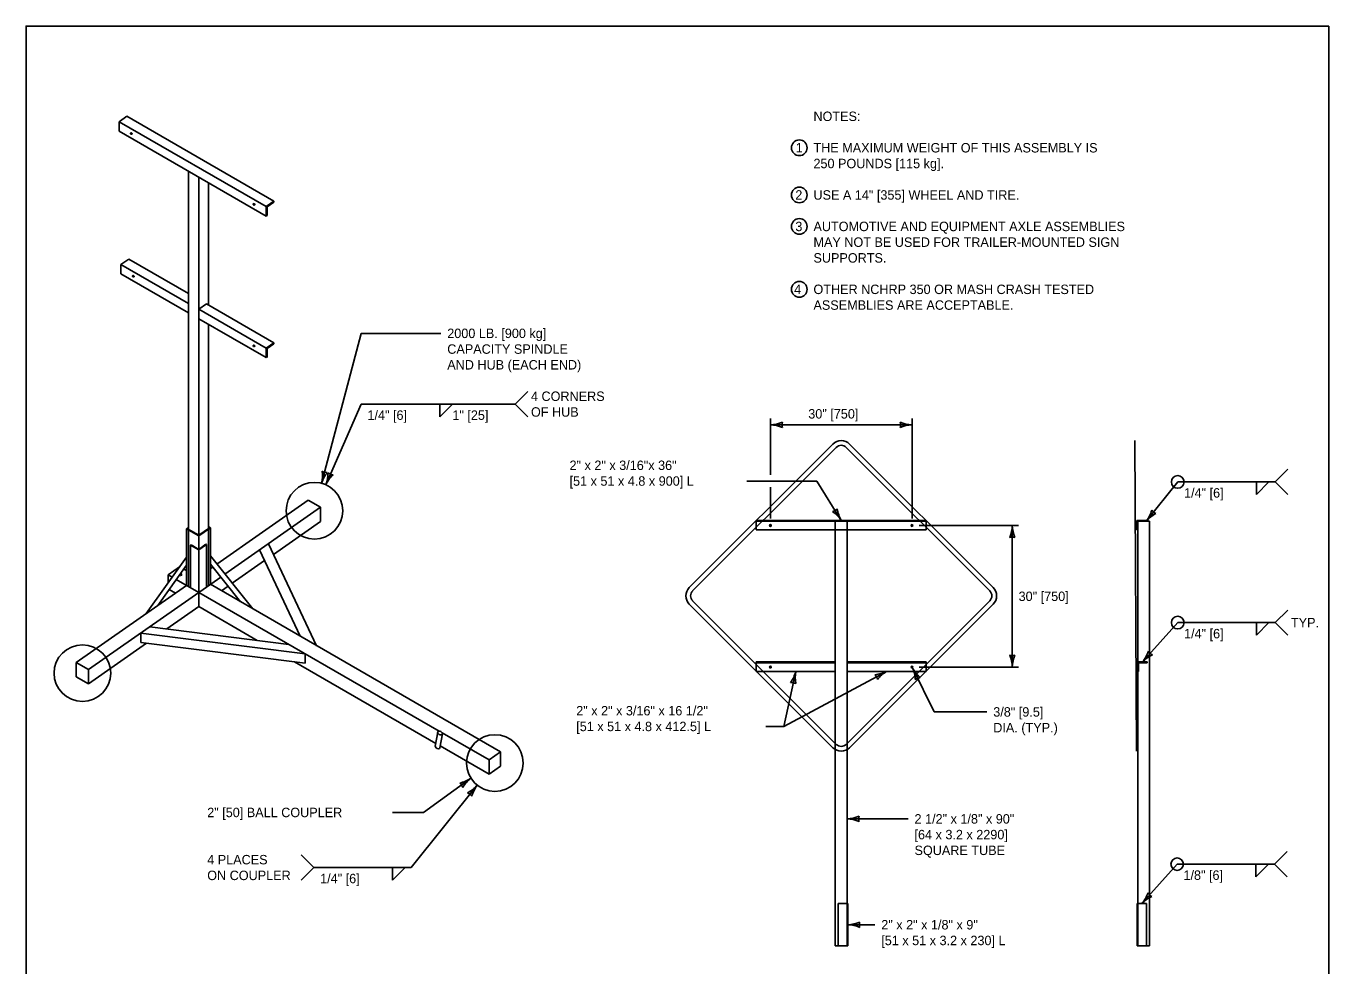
# Model space of a CAD drawing. Extents: x 49991.4 to 50021, y 49987.6 to 50011.4.
# Drawn here: x 50000.34 to 50008.61, y 50005.29 to 50011.26 of the extents above; entities that cross this region are included whole.
import ezdxf

# ---------------------------------------------------------------- set-up
doc = ezdxf.new("R2010")
doc.units = 0
for name, color, linetype in [('Level 1', 7, 'Continuous'), ('Level 2', 7, 'Continuous'), ('Level 3', 7, 'Continuous'), ('Level 4', 7, 'Continuous')]:
    doc.layers.add(name, color=color, linetype=linetype)

msp = doc.modelspace()

# ---------------------------------------------------------------- linework, layer by layer
at = {"layer": 'Level 1'}
for p, q in [((50000.9262, 50010.6548), (50000.9754, 50010.6891)), ((50000.9262, 50010.6548), (50001.8616, 50010.1148)), ((50000.9262, 50010.6548), (50000.9262, 50010.5948)), ((50000.9754, 50010.6891), (50001.9107, 50010.1491)), ((50000.9262, 50010.5948), (50001.8616, 50010.0548)), ((50001.3676, 50008.0639), (50001.3676, 50010.34)), ((50001.4329, 50008.0264), (50001.4329, 50010.3022)), ((50001.4941, 50009.4897), (50001.4941, 50010.267)), ((50001.8616, 50010.1148), (50001.9107, 50010.1491)), ((50001.8671, 50010.1131), (50001.9107, 50010.1436)), ((50001.9107, 50010.1491), (50001.9107, 50010.1436)), ((50001.8616, 50010.1148), (50001.8616, 50010.0548)), ((50001.8616, 50010.0548), (50001.8671, 50010.0586)), ((50001.8671, 50010.1131), (50001.8671, 50010.0586)), ((50000.9388, 50009.7475), (50000.988, 50009.7818)), ((50000.9388, 50009.7475), (50000.9388, 50009.6875)), ((50000.9388, 50009.7475), (50001.3676, 50009.4999)), ((50000.988, 50009.7818), (50001.3676, 50009.5627)), ((50000.9388, 50009.6875), (50001.3676, 50009.4399)), ((50001.4329, 50009.4622), (50001.4821, 50009.4967)), ((50001.4821, 50009.4967), (50001.9107, 50009.2491)), ((50001.4329, 50009.4622), (50001.8616, 50009.2148)), ((50001.4329, 50009.4022), (50001.8616, 50009.1548)), ((50001.4941, 50008.0692), (50001.4941, 50009.367)), ((50001.8616, 50009.2148), (50001.9107, 50009.2491)), ((50001.8671, 50009.2131), (50001.9107, 50009.2436)), ((50001.9107, 50009.2491), (50001.9107, 50009.2436)), ((50001.8616, 50009.2148), (50001.8616, 50009.1548)), ((50001.8616, 50009.1548), (50001.8671, 50009.1586)), ((50001.8671, 50009.2131), (50001.8671, 50009.1586)), ((50005.4624, 50008.6057), (50004.5501, 50007.6937)), ((50005.4839, 50008.5846), (50004.5714, 50007.6725)), ((50006.4595, 50007.6725), (50005.5475, 50008.5846)), ((50006.4807, 50007.6937), (50005.5682, 50008.6057)), ((50007.3805, 50008.6276), (50007.3927, 50006.6534)), ((50001.5481, 50007.8425), (50002.1291, 50008.2493)), ((50002.1291, 50008.2493), (50002.207, 50008.2043)), ((50001.5993, 50007.7788), (50002.207, 50008.2043)), ((50002.207, 50008.2043), (50002.207, 50008.1143)), ((50001.355, 50008.0672), (50001.3676, 50008.076)), ((50001.355, 50008.0672), (50001.4329, 50008.0222)), ((50001.355, 50007.7072), (50001.355, 50008.0672)), ((50001.3613, 50008.0675), (50001.3676, 50008.0719)), ((50001.3613, 50008.0675), (50001.4327, 50008.0263)), ((50001.4327, 50008.0263), (50001.5003, 50008.0736)), ((50001.4329, 50008.0222), (50001.5067, 50008.0738)), ((50001.4941, 50008.0812), (50001.5067, 50008.0738)), ((50001.4941, 50008.0772), (50001.5003, 50008.0736)), ((50001.5067, 50007.714), (50001.5067, 50008.0738)), ((50001.9073, 50007.9043), (50002.207, 50008.1143)), ((50004.9754, 50008.1206), (50006.0554, 50008.1206)), ((50004.9754, 50008.1206), (50004.9754, 50008.0606)), ((50004.9754, 50008.0606), (50006.0554, 50008.0606)), ((50005.4779, 50008.0606), (50005.4779, 50005.4151)), ((50005.5529, 50005.6851), (50005.5529, 50008.0606)), ((50006.0554, 50008.1206), (50006.0554, 50008.0606)), ((50007.394, 50008.1206), (50007.454, 50008.1206)), ((50007.394, 50008.0606), (50007.394, 50008.1206)), ((50007.3996, 50008.0606), (50007.394, 50008.0606)), ((50007.4746, 50008.1151), (50007.3996, 50008.1151)), ((50007.3996, 50008.1151), (50007.3996, 50005.6851)), ((50007.454, 50008.1151), (50007.454, 50008.1206)), ((50007.4746, 50008.1151), (50007.4746, 50005.4151)), ((50001.4329, 50007.6622), (50001.4329, 50008.0222)), ((50001.5067, 50007.894), (50001.7769, 50007.5579)), ((50001.8185, 50007.9322), (50002.0783, 50007.3839)), ((50001.8752, 50007.972), (50002.1822, 50007.3239)), ((50001.355, 50007.8872), (50001.0994, 50007.5283)), ((50001.355, 50007.8352), (50001.1732, 50007.58)), ((50001.238, 50007.7748), (50001.3113, 50007.8258)), ((50001.3379, 50007.8113), (50001.355, 50007.8014)), ((50001.5067, 50007.8419), (50001.6988, 50007.603)), ((50001.5067, 50007.8134), (50001.5213, 50007.8237)), ((50001.6456, 50007.7212), (50001.8505, 50007.8647)), ((50000.7325, 50007.1718), (50001.5726, 50007.76)), ((50001.238, 50007.7748), (50001.238, 50007.7229)), ((50001.238, 50007.7748), (50001.2641, 50007.7596)), ((50001.2904, 50007.7445), (50001.4329, 50007.6622)), ((50000.6545, 50007.2168), (50001.355, 50007.7072)), ((50001.245, 50007.6808), (50001.2845, 50007.6579)), ((50001.4329, 50007.6622), (50001.4329, 50007.5722)), ((50001.4329, 50007.6622), (50002.9596, 50006.7808)), ((50001.5067, 50007.714), (50003.3513, 50006.6488)), ((50001.5771, 50007.6732), (50001.6189, 50007.7024)), ((50006.4595, 50007.6724), (50006.4595, 50007.6725)), ((50006.4807, 50007.6936), (50006.4807, 50007.6937)), ((50001.2299, 50007.4301), (50001.4329, 50007.5722)), ((50001.4329, 50007.5722), (50001.8049, 50007.3574)), ((50004.5501, 50007.5874), (50005.4624, 50006.6754)), ((50004.5714, 50007.6089), (50005.4839, 50006.6964)), ((50005.5475, 50006.6964), (50006.4595, 50007.6089)), ((50005.5682, 50006.6754), (50006.4807, 50007.5874)), ((50001.0643, 50007.4041), (50002.1084, 50007.2722)), ((50001.0643, 50007.4041), (50001.0643, 50007.3441)), ((50001.1211, 50007.4438), (50002.0044, 50007.3322)), ((50000.7325, 50007.0818), (50001.1005, 50007.3395)), ((50001.0643, 50007.3441), (50002.1084, 50007.2122)), ((50002.1084, 50007.2722), (50002.1084, 50007.2122)), ((50000.6545, 50007.2168), (50000.6545, 50007.1268)), ((50000.6545, 50007.2168), (50000.7325, 50007.1718)), ((50000.7325, 50007.1718), (50000.7325, 50007.0818)), ((50002.0419, 50007.2206), (50002.9385, 50006.7029)), ((50005.4779, 50007.2206), (50004.9754, 50007.2206)), ((50004.9754, 50007.2206), (50004.9754, 50007.1606)), ((50005.4779, 50007.1606), (50004.9754, 50007.1606)), ((50006.0554, 50007.2206), (50005.5529, 50007.2206)), ((50006.0554, 50007.1606), (50005.5529, 50007.1606)), ((50006.0554, 50007.2206), (50006.0554, 50007.1606)), ((50007.3996, 50007.2206), (50007.4596, 50007.2206)), ((50007.4053, 50007.1606), (50007.3996, 50007.1606)), ((50007.4053, 50007.1606), (50007.4053, 50007.2151)), ((50007.4053, 50007.2151), (50007.4596, 50007.2151)), ((50007.4596, 50007.2151), (50007.4596, 50007.2206)), ((50000.6545, 50007.1268), (50000.7325, 50007.0818)), ((50002.9356, 50006.6861), (50002.9512, 50006.7748)), ((50002.9652, 50006.6746), (50002.9808, 50006.7632)), ((50002.9797, 50006.7692), (50003.2775, 50006.5972)), ((50002.9673, 50006.6864), (50003.2775, 50006.5072)), ((50003.3513, 50006.6488), (50003.2775, 50006.5972)), ((50003.2775, 50006.5972), (50003.2775, 50006.5072)), ((50003.3513, 50006.6488), (50003.3513, 50006.5588)), ((50003.3513, 50006.5588), (50003.2775, 50006.5072)), ((50005.5566, 50005.6851), (50005.4966, 50005.6851)), ((50005.4966, 50005.4151), (50005.4966, 50005.6851)), ((50005.5566, 50005.4151), (50005.5566, 50005.6851)), ((50007.3959, 50005.4151), (50007.3959, 50005.6851)), ((50007.3959, 50005.6851), (50007.4559, 50005.6851)), ((50007.4559, 50005.4151), (50007.4559, 50005.6851)), ((50005.4779, 50005.4151), (50005.5566, 50005.4151)), ((50007.3959, 50005.4151), (50007.4746, 50005.4151))]:
    msp.add_line(p, q, dxfattribs=at)
msp.add_lwpolyline([(50008.6146, 50011.2628), (50000.3356, 50011.2628), (50000.3356, 50000.0624), (50008.6146, 50000.0624)], close=True, dxfattribs=at)
for centre in [(50005.0654, 50008.0878), (50005.9654, 50008.0878), (50005.0654, 50007.1878), (50005.9654, 50007.1878)]:
    msp.add_circle(centre, 0.00563, dxfattribs=at)
for centre, radius, start, end in [((50005.5155, 50008.5527), 0.075, 45, 135), ((50005.5155, 50008.5527), 0.045, 45, 135), ((50004.6033, 50007.6405), 0.075, 135, 225), ((50004.6033, 50007.6405), 0.045, 135, 225), ((50006.4276, 50007.6405), 0.045, 315, 45.00024), ((50006.4276, 50007.6405), 0.075, 315, 45.00024), ((50005.5155, 50006.7284), 0.075, 225, 314.99957), ((50005.5155, 50006.7284), 0.045, 225, 314.99957)]:
    msp.add_arc(centre, radius, start, end, dxfattribs=at)
for centre, major_axis, ratio in [((50001.0042, 50010.5797), (-0.00487, 0.00281), 0.793889), ((50001.7836, 50010.1298), (-0.00487, 0.00281), 0.793889), ((50001.0168, 50009.6724), (-0.00487, 0.00281), 0.793889), ((50001.7836, 50009.2298), (-0.00487, 0.00281), 0.793889), ((50002.966, 50006.769), (0.0141, -0.0078), 0.627424)]:
    msp.add_ellipse(centre, major_axis=major_axis, ratio=ratio, dxfattribs=at)
for centre, major_axis, ratio, start_param, end_param in [((50001.3139, 50007.7781), (-0.00974, 0.00562), 0.671339, 1.537184, 4.61786), ((50002.9504, 50006.6803), (0.0141, -0.0078), 0.627424, 3.356004, 6.497597)]:
    msp.add_ellipse(centre, major_axis=major_axis, ratio=ratio, start_param=start_param, end_param=end_param, dxfattribs=at)
at = {"layer": 'Level 2'}
for centre in [(50005.249, 50010.4891), (50005.249, 50010.1891), (50005.249, 50009.9891), (50005.249, 50009.5891)]:
    msp.add_circle(centre, 0.05, dxfattribs=at)
at = {"layer": 'Level 3'}
for p, q in [((50002.2138, 50008.3558), (50002.4649, 50009.3094)), ((50002.9721, 50009.3094), (50002.4649, 50009.3094)), ((50003.444, 50008.8594), (50003.524, 50008.9394)), ((50002.4649, 50008.8594), (50002.2402, 50008.3466)), ((50002.4649, 50008.8594), (50003.444, 50008.8594)), ((50002.9644, 50008.8594), (50002.9644, 50008.7794)), ((50002.9644, 50008.7794), (50003.0444, 50008.8594)), ((50003.444, 50008.8594), (50003.524, 50008.7794)), ((50005.0654, 50008.4106), (50005.0654, 50008.7677)), ((50005.0654, 50008.7277), (50005.9654, 50008.7277)), ((50005.9654, 50008.1334), (50005.9654, 50008.7677)), ((50008.2733, 50008.3651), (50008.3533, 50008.4451)), ((50004.9154, 50008.3706), (50005.3602, 50008.3706)), ((50005.0654, 50008.1334), (50005.0654, 50008.3306)), ((50005.3602, 50008.3706), (50005.5154, 50008.1206)), ((50007.454, 50008.1151), (50007.6538, 50008.3651)), ((50007.6538, 50008.3651), (50008.2733, 50008.3651)), ((50008.1533, 50008.3651), (50008.1533, 50008.2851)), ((50008.1533, 50008.2851), (50008.2333, 50008.3651)), ((50008.2733, 50008.3651), (50008.3533, 50008.2851)), ((50006.011, 50008.0878), (50006.6426, 50008.0878)), ((50006.6026, 50008.0878), (50006.6026, 50007.1878)), ((50008.2733, 50007.4706), (50008.3533, 50007.5506)), ((50007.4296, 50007.2206), (50007.6538, 50007.4706)), ((50007.6538, 50007.4706), (50008.2733, 50007.4706)), ((50008.1533, 50007.4706), (50008.1533, 50007.3906)), ((50008.1533, 50007.3906), (50008.2333, 50007.4706)), ((50008.2733, 50007.4706), (50008.3533, 50007.3906)), ((50005.15, 50006.8106), (50005.8042, 50007.1606)), ((50005.15, 50006.8106), (50005.2266, 50007.1606)), ((50006.1065, 50006.9028), (50005.9679, 50007.1828)), ((50006.011, 50007.1878), (50006.6426, 50007.1878)), ((50006.1065, 50006.9028), (50006.4416, 50006.9028)), ((50005.15, 50006.8106), (50005.0354, 50006.8106)), ((50003.2021, 50006.4374), (50002.7836, 50005.9137)), ((50003.1625, 50006.4815), (50002.8616, 50006.2637)), ((50002.6635, 50006.2637), (50002.8616, 50006.2637)), ((50005.5529, 50006.223), (50005.9412, 50006.223)), ((50002.0841, 50005.9937), (50002.1641, 50005.9137)), ((50008.2696, 50005.9351), (50008.3496, 50006.0151)), ((50002.0841, 50005.8337), (50002.1641, 50005.9137)), ((50002.1641, 50005.9137), (50002.7836, 50005.9137)), ((50002.6636, 50005.9137), (50002.6636, 50005.8337)), ((50002.6636, 50005.8337), (50002.7436, 50005.9137)), ((50007.4259, 50005.6851), (50007.6501, 50005.9351)), ((50007.6501, 50005.9351), (50008.2696, 50005.9351)), ((50008.1496, 50005.8551), (50008.2296, 50005.9351)), ((50008.1496, 50005.9351), (50008.1496, 50005.8551)), ((50008.2696, 50005.9351), (50008.3496, 50005.8551)), ((50005.5566, 50005.5501), (50005.73, 50005.5501))]:
    msp.add_line(p, q, dxfattribs=at)
for centre, radius in [((50007.6538, 50008.3651), 0.04), ((50002.168, 50008.1817), 0.18), ((50007.6538, 50007.4706), 0.04), ((50000.6936, 50007.1492), 0.18), ((50003.3145, 50006.578), 0.18), ((50007.6501, 50005.9351), 0.04)]:
    msp.add_circle(centre, radius, dxfattribs=at)
for centre, radius, start, end in [((50005.0539, 50008.9604), 0.233, 272.82731, 292.07716), ((50005.0563, 50008.5056), 0.2223, 67.45601, 87.63952), ((50005.1936, 50008.7277), 0.0548, 162.13882, 197.86118), ((50005.9746, 50008.9498), 0.2223, 247.45601, 267.63952), ((50005.8372, 50008.7277), 0.0548, 342.13882, 17.86118), ((50005.9769, 50008.495), 0.233, 92.82731, 112.07716), ((50001.9858, 50008.4039), 0.233, 348.07577, 7.32562), ((50002.4263, 50008.2904), 0.2223, 142.70447, 162.88798), ((50002.2464, 50008.4798), 0.0548, 237.38728, 273.10964), ((50002.0225, 50008.4295), 0.233, 339.16619, 358.41604), ((50002.44, 50008.2491), 0.2223, 133.79489, 153.9784), ((50002.2917, 50008.464), 0.0548, 228.4777, 264.20006), ((50005.4478, 50008.2295), 0.0548, 283.97083, 319.69319), ((50005.3238, 50007.9881), 0.233, 34.65932, 53.90917), ((50005.709, 50008.23), 0.2223, 189.28802, 209.47153), ((50007.2651, 50008.2514), 0.233, 324.19546, 343.44531), ((50007.6218, 50007.9693), 0.2223, 118.82416, 139.00767), ((50007.5341, 50008.2153), 0.0548, 213.50697, 249.22933), ((50006.3805, 50008.097), 0.2223, 337.45601, 357.63952), ((50006.8353, 50008.0993), 0.233, 182.82731, 202.07716), ((50006.6026, 50007.9596), 0.0548, 72.13882, 107.86118), ((50006.6026, 50007.316), 0.0548, 252.13882, 287.86118), ((50006.3699, 50007.1763), 0.233, 2.82731, 22.07716), ((50006.8248, 50007.1786), 0.2223, 157.45601, 177.63952), ((50007.2487, 50007.3674), 0.233, 320.94156, 340.19141), ((50007.5889, 50007.0655), 0.2223, 115.57026, 135.75377), ((50007.5152, 50007.3161), 0.0548, 210.25307, 245.97543), ((50005.0116, 50007.217), 0.2223, 325.10903, 345.29254), ((50005.4564, 50007.122), 0.233, 170.48033, 189.73018), ((50005.7075, 50007.3608), 0.2223, 275.60325, 295.78676), ((50005.9241, 50006.9608), 0.233, 120.97455, 140.2244), ((50005.7648, 50007.0925), 0.2223, 3.79142, 23.97493), ((50006.1714, 50007.2963), 0.233, 209.16272, 228.41257), ((50005.1992, 50007.0353), 0.0548, 59.79184, 95.5142), ((50005.6912, 50007.1001), 0.0548, 10.28606, 46.00842), ((50006.0248, 50007.0679), 0.0548, 98.47423, 134.19659), ((50003.0397, 50006.6668), 0.2223, 283.3541, 303.53761), ((50003.0587, 50006.4063), 0.0548, 18.03691, 53.75927), ((50003.3083, 50006.2997), 0.233, 128.7254, 147.97525), ((50003.0343, 50006.5832), 0.2223, 298.8269, 319.01041), ((50003.3911, 50006.3011), 0.233, 144.1982, 163.44805), ((50003.1221, 50006.3373), 0.0548, 33.50971, 69.23207), ((50005.5414, 50006.4557), 0.233, 272.82731, 292.07716), ((50005.6811, 50006.223), 0.0548, 162.13882, 197.86118), ((50005.5438, 50006.0009), 0.2223, 67.45601, 87.63952), ((50007.245, 50005.8319), 0.233, 320.94156, 340.19141), ((50007.5115, 50005.7806), 0.0548, 210.25307, 245.97543), ((50007.5852, 50005.53), 0.2223, 115.57026, 135.75377), ((50005.5451, 50005.7828), 0.233, 272.82731, 292.07716), ((50005.5475, 50005.328), 0.2223, 67.45601, 87.63952), ((50005.6848, 50005.5501), 0.0548, 162.13882, 197.86118)]:
    msp.add_arc(centre, radius, start, end, dxfattribs=at)
at = {"layer": 'Level 4'}
for p, q in [((50001.3676, 50008.0639), (50001.3676, 50007.7)), ((50001.4941, 50008.0692), (50001.4941, 50007.705)), ((50004.9754, 50008.1151), (50006.0554, 50008.1151)), ((50005.4779, 50008.1151), (50005.4779, 50008.0606)), ((50005.5529, 50008.0606), (50005.5529, 50008.1151)), ((50001.3809, 50007.9622), (50001.384, 50007.9643)), ((50001.3809, 50007.9622), (50001.4329, 50007.9322)), ((50001.3809, 50007.9622), (50001.3809, 50007.6923)), ((50001.384, 50007.9643), (50001.4327, 50007.9362)), ((50001.4327, 50007.9362), (50001.4788, 50007.9684)), ((50001.4329, 50007.9322), (50001.482, 50007.9666)), ((50001.4788, 50007.9684), (50001.482, 50007.9666)), ((50001.482, 50007.9666), (50001.482, 50007.6966)), ((50005.4779, 50007.2151), (50004.9754, 50007.2151)), ((50006.0554, 50007.2151), (50005.5529, 50007.2151)), ((50005.5529, 50005.4151), (50005.5529, 50005.6851)), ((50007.3996, 50005.4151), (50007.3996, 50005.6851))]:
    msp.add_line(p, q, dxfattribs=at)

# ---------------------------------------------------------------- texts
at = {"layer": 'Level 2'}
for s, p in [('NOTES:', (50005.339, 50010.6591)), ('1', (50005.2264, 50010.4591)), ('THE MAXIMUM WEIGHT OF THIS ASSEMBLY IS', (50005.339, 50010.4591)), ('250 POUNDS [115 kg].', (50005.339, 50010.3591)), ('2', (50005.2239, 50010.1591)), ('USE A 14" [355] WHEEL AND TIRE.', (50005.339, 50010.1591)), ('3', (50005.2238, 50009.9591)), ('AUTOMOTIVE AND EQUIPMENT AXLE ASSEMBLIES', (50005.339, 50009.9591)), ('MAY NOT BE USED FOR TRAILER-MOUNTED SIGN', (50005.339, 50009.8591)), ('SUPPORTS.', (50005.339, 50009.7591)), ('4', (50005.2163, 50009.5591)), ('OTHER NCHRP 350 OR MASH CRASH TESTED ', (50005.339, 50009.5591)), ('ASSEMBLIES ARE ACCEPTABLE.', (50005.339, 50009.4591)), ('2000 LB. [900 kg] ', (50003.0121, 50009.2794)), ('CAPACITY SPINDLE', (50003.0121, 50009.1794)), ('AND HUB (EACH END)', (50003.0121, 50009.0794)), ('4 CORNERS', (50003.544, 50008.8796)), ('1/4" [6]', (50002.5049, 50008.7594)), ('1" [25]', (50003.0444, 50008.7594)), ('OF HUB', (50003.544, 50008.7796)), ('30" [750]', (50005.306, 50008.7677)), ('2" x 2" x 3/16"x 36" ', (50003.7891, 50008.4406)), ('[51 x 51 x 4.8 x 900] L', (50003.7891, 50008.3406)), ('1/4" [6]', (50007.6938, 50008.2651)), ('30" [750]', (50006.6426, 50007.6078)), ('TYP.', (50008.3733, 50007.4406)), ('1/4" [6]', (50007.6938, 50007.3706)), ('2" x 2" x 3/16" x 16 1/2" ', (50003.8316, 50006.8806)), ('3/8" [9.5]', (50006.4816, 50006.8728)), ('[51 x 51 x 4.8 x 412.5] L', (50003.8316, 50006.7806)), ('DIA. (TYP.)', (50006.4816, 50006.7728)), ('2" [50] BALL COUPLER', (50001.4868, 50006.2337)), ('2 1/2" x 1/8" x 90"', (50005.9812, 50006.193)), ('[64 x 3.2 x 2290]', (50005.9812, 50006.093)), ('4 PLACES', (50001.4868, 50005.9337)), ('SQUARE TUBE', (50005.9812, 50005.993)), ('ON COUPLER', (50001.4868, 50005.8337)), ('1/4" [6]', (50002.2041, 50005.8137)), ('1/8" [6]', (50007.6901, 50005.8351)), ('2" x 2" x 1/8" x 9" ', (50005.77, 50005.5201)), ('[51 x 51 x 3.2 x 230] L', (50005.77, 50005.4201))]:
    msp.add_text(s, height=0.06, dxfattribs=at).set_placement(p)

doc.saveas('drawing.dxf')
